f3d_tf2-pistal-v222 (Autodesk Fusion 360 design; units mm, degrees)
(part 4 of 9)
sketch "Sketch61" plane through (12.7981, 0, 0) normal (1, 0, 0) x axis (0, 1, 0)
  line L1 (189.658, -22.0959) -> (189.51, -21.9548)
  curve K1 (190.0964, -23.2203) -> (189.658, -22.0959)
  curve K2 (188.683, -22.9135) -> (189.7139, -23.5411)
  line L2 (188.5699, -22.7433) -> (188.683, -22.9135)
  line L3 (187.8606, -23.3644) -> (187.778, -23.1775)
  curve K3 (187.8354, -24.571) -> (187.8606, -23.3644)
  curve K4 (186.647, -23.7467) -> (187.3593, -24.721)
  line L4 (186.6076, -23.5461) -> (186.647, -23.7467)
  line L5 (185.7147, -23.8486) -> (185.7098, -23.6442)
  curve K5 (185.2296, -24.9537) -> (185.7147, -23.8486)
  curve K6 (184.4472, -23.7374) -> (184.7324, -24.91)
  line L6 (184.4875, -23.537) -> (184.4472, -23.7374)
  line L7 (183.5468, -23.4747) -> (183.6205, -23.284)
  curve K7 (182.6757, -24.31) -> (183.5468, -23.4747)
  curve K8 (182.4183, -22.8869) -> (182.233, -24.0794)
  line L8 (182.5323, -22.7172) -> (182.4183, -22.8869)
  line L9 (181.687, -22.2996) -> (181.8281, -22.1517)
  curve K9 (180.5626, -22.738) -> (181.687, -22.2996)
  curve K10 (180.8694, -21.3247) -> (180.2419, -22.3555)
  line L10 (181.0396, -21.2115) -> (180.8694, -21.3247)
  line L11 (180.4185, -20.5023) -> (180.6054, -20.4196)
  curve K11 (179.2119, -20.477) -> (180.4185, -20.5023)
  curve K12 (180.0362, -19.2887) -> (179.0619, -20.0009)
  line L12 (180.2368, -19.2493) -> (180.0362, -19.2887)
  line L13 (179.9343, -18.3563) -> (180.1387, -18.3515)
  curve K13 (178.8293, -17.8713) -> (179.9343, -18.3563)
  curve K14 (180.0455, -17.0888) -> (178.8729, -17.374)
  line L14 (180.246, -17.1292) -> (180.0455, -17.0888)
  line L15 (180.3082, -16.1884) -> (180.4989, -16.2622)
  curve K15 (179.4729, -15.3174) -> (180.3082, -16.1884)
  curve K16 (180.8961, -15.06) -> (179.7035, -14.8747)
  line L16 (181.0658, -15.1739) -> (180.8961, -15.06)
  line L17 (181.4833, -14.3287) -> (181.6312, -14.4698)
  curve K17 (181.0449, -13.2043) -> (181.4833, -14.3287)
  curve K18 (182.4582, -13.511) -> (181.4274, -12.8835)
  line L18 (182.5714, -13.6813) -> (182.4582, -13.511)
  line L19 (183.2806, -13.0601) -> (183.3633, -13.2471)
  curve K19 (183.3059, -11.8536) -> (183.2806, -13.0601)
  curve K20 (184.4942, -12.6778) -> (183.782, -11.7036)
  line L20 (184.5336, -12.8784) -> (184.4942, -12.6778)
  line L21 (185.4266, -12.576) -> (185.4314, -12.7803)
  curve K21 (185.9117, -11.4709) -> (185.4266, -12.576)
  curve K22 (186.6941, -12.6872) -> (186.4089, -11.5145)
  line L22 (186.6538, -12.8876) -> (186.6941, -12.6872)
  line L23 (187.5945, -12.9499) -> (187.5207, -13.1406)
  curve K23 (188.4655, -12.1146) -> (187.5945, -12.9499)
  curve K24 (188.723, -13.5377) -> (188.9082, -12.3452)
  line L24 (188.609, -13.7074) -> (188.723, -13.5377)
  line L25 (189.4543, -14.125) -> (189.3132, -14.2729)
  curve K25 (190.5787, -13.6866) -> (189.4543, -14.125)
  curve K26 (190.2719, -15.0999) -> (190.8994, -14.069)
  line L26 (190.1016, -15.2131) -> (190.2719, -15.0999)
  line L27 (190.7228, -15.9223) -> (190.5358, -16.005)
  curve K27 (191.9294, -15.9475) -> (190.7228, -15.9223)
  curve K28 (191.1051, -17.1359) -> (192.0793, -16.4236)
  line L28 (190.9045, -17.1753) -> (191.1051, -17.1359)
  line L29 (191.207, -18.0682) -> (191.0026, -18.0731)
  curve K29 (192.312, -18.5533) -> (191.207, -18.0682)
  curve K30 (191.0957, -19.3358) -> (192.2684, -19.0506)
  line L30 (190.8953, -19.2954) -> (191.0957, -19.3358)
  line L31 (190.833, -20.2361) -> (190.6424, -20.1624)
  curve K31 (191.6684, -21.1072) -> (190.833, -20.2361)
  curve K32 (190.2452, -21.3646) -> (191.4377, -21.5499)
  line L32 (190.0755, -21.2506) -> (190.2452, -21.3646)
  line L33 (187.271, -51.9985) -> (187.2458, -51.5038)
  curve K33 (189.5851, -57.0051) -> (187.271, -51.9985)
  curve K34 (192.6554, -51.291) -> (191.7132, -56.7255)
  line L34 (192.552, -50.8067) -> (192.6554, -51.291)
  line L35 (195.9575, -50.4071) -> (195.8052, -49.9359)
  curve K35 (199.4886, -54.6443) -> (195.9575, -50.4071)
  curve K36 (200.9754, -48.3302) -> (201.4718, -53.8234)
  line L36 (200.7501, -47.8891) -> (200.9754, -48.3302)
  line L37 (203.9362, -46.6218) -> (203.6671, -46.206)
  curve K37 (208.4437, -49.8007) -> (203.9362, -46.6218)
  curve K38 (208.2456, -43.3169) -> (210.1468, -48.4945)
  line L38 (207.9138, -42.9492) -> (208.2456, -43.3169)
  line L39 (210.6634, -40.9004) -> (210.2958, -40.5684)
  curve K39 (215.8399, -42.8043) -> (210.6634, -40.9004)
  curve K40 (213.9705, -36.5928) -> (217.147, -41.1018)
  line L40 (213.5549, -36.3234) -> (213.9705, -36.5928)
  line L41 (215.6805, -33.6328) -> (215.2395, -33.4073)
  curve K41 (221.1734, -34.1321) -> (215.6805, -33.6328)
  curve K42 (217.7601, -28.616) -> (221.9953, -32.1493)
  line L42 (217.2889, -28.4635) -> (217.7601, -28.616)
  line L43 (218.6457, -25.3144) -> (218.1614, -25.2107)
  curve K43 (224.0807, -24.375) -> (218.6457, -25.3144)
  curve K44 (219.3559, -19.9303) -> (224.3614, -22.247)
  line L44 (218.8613, -19.9049) -> (219.3559, -19.9303)
  line L45 (219.3568, -16.512) -> (218.8622, -16.5371)
  curve K45 (224.3635, -14.1979) -> (219.3568, -16.512)
  curve K46 (218.6494, -11.1275) -> (224.0839, -12.0698)
  line L46 (218.165, -11.231) -> (218.6494, -11.1275)
  line L47 (217.7655, -7.8254) -> (217.2942, -7.9777)
  curve K47 (222.0026, -4.2943) -> (217.7655, -7.8254)
  curve K48 (215.6886, -2.8075) -> (221.1818, -2.3111)
  line L48 (215.2475, -3.0328) -> (215.6886, -2.8075)
  line L49 (213.9802, 0.1533) -> (213.5644, -0.1158)
  curve K49 (217.159, 4.6607) -> (213.9802, 0.1533)
  curve K50 (210.6753, 4.4627) -> (215.8528, 6.3639)
  line L50 (210.3075, 4.1309) -> (210.6753, 4.4627)
  line L51 (208.2588, 6.8805) -> (207.9268, 6.5129)
  curve K51 (210.1627, 12.057) -> (208.2588, 6.8805)
  curve K52 (203.9511, 10.1876) -> (208.4602, 13.3641)
  line L52 (203.6818, 9.772) -> (203.9511, 10.1876)
  line L53 (200.9912, 11.8976) -> (200.7657, 11.4566)
  curve K53 (201.4905, 17.3905) -> (200.9912, 11.8976)
  curve K54 (195.9744, 13.9771) -> (199.5077, 18.2124)
  line L54 (195.8218, 13.5059) -> (195.9744, 13.9771)
  line L55 (192.6728, 14.8627) -> (192.569, 14.3784)
  curve K55 (191.7333, 20.2977) -> (192.6728, 14.8627)
  curve K56 (187.2887, 15.573) -> (189.6054, 20.5784)
  line L56 (187.2632, 15.0784) -> (187.2887, 15.573)
  line L57 (183.8703, 15.5739) -> (183.8955, 15.0793)
  curve K57 (181.5562, 20.5806) -> (183.8703, 15.5739)
  curve K58 (178.4858, 14.8664) -> (179.4281, 20.301)
  line L58 (178.5893, 14.3821) -> (178.4858, 14.8664)
  line L59 (175.1837, 13.9826) -> (175.3361, 13.5113)
  curve K59 (171.6527, 18.2197) -> (175.1837, 13.9826)
  curve K60 (170.1658, 11.9056) -> (169.6695, 17.3988)
  line L60 (170.3911, 11.4646) -> (170.1658, 11.9056)
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copy_paste_bodies "CopyPasteBodies4"
delete_face "DeleteFace52"
split "Split23"
delete_face "DeleteFace53"
delete_face "DeleteFace54"
move "Move3"
move "Move45"
sketch "Sketch62" plane through (9.6845, 0, 0) normal (1, 0, 0) x axis (0, 1, 0)
  line L1 (154.482, 22.4851) -> (154.482, 14)
  line L2 (20.5955, 22.4851) -> (154.482, 22.4851)
  line L3 (20.5955, 2.4851) -> (20.5955, 22.4851)
  line L4 (154.482, 2.4851) -> (20.5955, 2.4851)
  line L5 (154.482, 10) -> (154.482, 2.4851)
  line L6 (87.482, 10) -> (154.482, 10)
  line L7 (153.482, 13) -> (87.482, 13)
  arc A1 centre (87.482, 11.5) radius 1.5 clockwise from (87.482, 10) to (87.482, 13)
  arc A2 centre (153.482, 14) radius 1 clockwise from (154.482, 14) to (153.482, 13)
move "Move46" RotateAngle -30
move "Move4"
move "Move47" TranslateX 0 TranslateY -2 TranslateZ 0
combine "Combine51"
combine "Combine52"
delete_face "DeleteFace55"
delete_face "DeleteFace56"
fillet "Fillet76" radius 2
move_face "MoveFace72"
move "Move48"
move_face "MoveFace73"
move_face "MoveFace74"
move_face "MoveFace75"
move_face "MoveFace76"
delete_face "DeleteFace57"
move "Move5"
sketch "Sketch63" plane through (0, 18.7817, 0) normal (0, -1, 0) x axis (1, 0, 0)
  line L1 (8.6845, 2.4851) -> (-8.4524, 2.4851)
  line L2 (8.6845, 22.4851) -> (8.6845, 2.4851)
  line L3 (-8.4524, 22.4851) -> (8.6845, 22.4851)
  line L4 (-8.4524, 2.4851) -> (-8.4524, 22.4851)
  circle C1 centre (0, 12.7351) radius 5.9036
extrude "Extrude56" cut sketch "Sketch63" profile of C1 against normal blind 133.887
offset_faces "OffsetFaces8" distance -1
fillet "Fillet77" radius 1.5
fillet "Fillet78" radius 0.5
fillet "Fillet79" radius 0.5
delete_face "DeleteFace58"
move_face "MoveFace77"
delete_face "DeleteFace59"
move_face "MoveFace78"
move_face "MoveFace79"
move_face "MoveFace80"
remove_body "RemoveBody17"
copy_paste_bodies "CopyPasteBodies5"
copy_paste_bodies "CopyPasteBodies6"
move "Move49"
move "Move50"
delete_face "DeleteFace60"
delete_face "DeleteFace61"
delete_face "DeleteFace62"
move_face "MoveFace81"
delete_face "DeleteFace63"
move_face "MoveFace2"
combine "Combine53" bodies "Grip base"
remove_body "RemoveBody18"
combine "Combine54"
remove_body "RemoveBody19"
remove_body "RemoveBody20"
remove_body "RemoveBody21"
split "Split24"
remove_body "RemoveBody1"
remove_body "RemoveBody22"
remove_body "RemoveBody23"
move "Move51"
move_face "MoveFace3"
remove_body "RemoveBody24"
remove_body "RemoveBody25"
copy_paste_bodies "CopyPasteBodies8"
move "Move52"
combine "Combine55"
delete_face "DeleteFace64"
extrude "Extrude57" add of existing geometry blind 10
move_face "MoveFace83"
sketch "Sketch64" plane through (12.7981, 0, 0) normal (1, 0, 0) x axis (0, 1, 0)
  line L1 (89.7253, 20.0686) -> (89.7649, 20.5623)
  curve K1 (91.3661, 14.8028) -> (89.7253, 20.0686)
  curve K2 (95.156, 20.0672) -> (93.5125, 14.8022)
  line L2 (95.1167, 20.5609) -> (95.156, 20.0672)
  line L3 (98.2082, 21.6343) -> (96.0036, 21.6343)
  line L4 (99.0393, 20.0686) -> (99.0789, 20.5623)
  curve K3 (100.6801, 14.8028) -> (99.0393, 20.0686)
  curve K4 (104.47, 20.0672) -> (102.8265, 14.8022)
  line L5 (104.4307, 20.5609) -> (104.47, 20.0672)
  line L6 (107.5222, 21.6343) -> (105.3176, 21.6343)
  line L7 (108.3533, 20.0686) -> (108.3929, 20.5623)
  curve K5 (109.9941, 14.8028) -> (108.3533, 20.0686)
  curve K6 (113.784, 20.0672) -> (112.1405, 14.8022)
  line L8 (113.7447, 20.5609) -> (113.784, 20.0672)
  line L9 (116.8362, 21.6343) -> (114.6316, 21.6343)
  line L10 (117.6673, 20.0686) -> (117.7069, 20.5623)
  curve K7 (119.3081, 14.8028) -> (117.6673, 20.0686)
  curve K8 (123.098, 20.0672) -> (121.4545, 14.8022)
  line L11 (123.0587, 20.5609) -> (123.098, 20.0672)
  line L12 (126.1502, 21.6343) -> (123.9456, 21.6343)
  line L13 (126.9813, 20.0686) -> (127.0209, 20.5623)
  curve K9 (128.6221, 14.8028) -> (126.9813, 20.0686)
  curve K10 (132.412, 20.0672) -> (130.7685, 14.8022)
  line L14 (132.3727, 20.5609) -> (132.412, 20.0672)
  line L15 (135.4642, 21.6343) -> (133.2596, 21.6343)
  line L16 (136.2953, 20.0686) -> (136.3349, 20.5623)
  curve K11 (137.9361, 14.8028) -> (136.2953, 20.0686)
  curve K12 (141.726, 20.0672) -> (140.0825, 14.8022)
  line L17 (141.6867, 20.5609) -> (141.726, 20.0672)
  line L18 (144.7782, 21.6343) -> (142.5736, 21.6343)
  line L19 (145.6093, 20.0686) -> (145.6489, 20.5623)
  curve K13 (147.2501, 14.8028) -> (145.6093, 20.0686)
  curve K14 (151.04, 20.0672) -> (149.3965, 14.8022)
  line L20 (151.0007, 20.5609) -> (151.04, 20.0672)
  line L21 (154.0922, 21.6343) -> (151.8876, 21.6343)
  line L22 (154.9233, 20.0686) -> (154.9629, 20.5623)
  curve K15 (156.5641, 14.8028) -> (154.9233, 20.0686)
  curve K16 (160.354, 20.0672) -> (158.7105, 14.8022)
  line L23 (160.3147, 20.5609) -> (160.354, 20.0672)
  line L24 (163.4062, 21.6343) -> (161.2016, 21.6343)
  line L25 (164.2373, 20.0686) -> (164.2769, 20.5623)
  curve K17 (165.8781, 14.8028) -> (164.2373, 20.0686)
  curve K18 (169.668, 20.0672) -> (168.0245, 14.8022)
  line L26 (169.6287, 20.5609) -> (169.668, 20.0672)
  line L27 (172.7202, 21.6343) -> (170.5156, 21.6343)
  line L28 (173.5513, 20.0686) -> (173.5909, 20.5623)
  curve K19 (175.1921, 14.8028) -> (173.5513, 20.0686)
  curve K20 (178.982, 20.0672) -> (177.3385, 14.8022)
  line L29 (178.9427, 20.5609) -> (178.982, 20.0672)
  line L30 (182.0342, 21.6343) -> (179.8296, 21.6343)
  line L31 (182.8653, 20.0686) -> (182.9049, 20.5623)
  curve K21 (184.5061, 14.8028) -> (182.8653, 20.0686)
  curve K22 (188.296, 20.0672) -> (186.6525, 14.8022)
  line L32 (188.2567, 20.5609) -> (188.296, 20.0672)
  line L33 (189.1436, 25) -> (189.1436, 21.6343)
  line L34 (79.058, 25) -> (189.1436, 25)
  line L35 (79.058, 21.5994) -> (79.058, 25)
  line L36 (89.058, 21.5994) -> (79.058, 21.5994)
  line L37 (79.058, 3.4244) -> (79.058, 21.5994)
  line L38 (84.058, 3.4244) -> (79.058, 3.4244)
  line L39 (84.058, 21.5994) -> (84.058, 3.4244)
  arc A1 centre (88.7681, 20.6423) radius 1 clockwise from (89.058, 21.5994) to (89.7649, 20.5623)
  arc A2 centre (92.4495, 53.7877) radius 39 clockwise from (93.5125, 14.8022) to (91.3661, 14.8028)
  arc A3 centre (96.1135, 20.6404) radius 1 clockwise from (95.1167, 20.5609) to (96.0036, 21.6343)
  arc A4 centre (98.0821, 20.6423) radius 1 clockwise from (98.2082, 21.6343) to (99.0789, 20.5623)
  arc A5 centre (101.7635, 53.7877) radius 39 clockwise from (102.8265, 14.8022) to (100.6801, 14.8028)
  arc A6 centre (105.4275, 20.6404) radius 1 clockwise from (104.4307, 20.5609) to (105.3176, 21.6343)
  arc A7 centre (107.3961, 20.6423) radius 1 clockwise from (107.5222, 21.6343) to (108.3929, 20.5623)
  arc A8 centre (111.0775, 53.7877) radius 39 clockwise from (112.1405, 14.8022) to (109.9941, 14.8028)
  arc A9 centre (114.7415, 20.6404) radius 1 clockwise from (113.7447, 20.5609) to (114.6316, 21.6343)
  arc A10 centre (116.7101, 20.6423) radius 1 clockwise from (116.8362, 21.6343) to (117.7069, 20.5623)
  arc A11 centre (120.3915, 53.7877) radius 39 clockwise from (121.4545, 14.8022) to (119.3081, 14.8028)
  arc A12 centre (124.0555, 20.6404) radius 1 clockwise from (123.0587, 20.5609) to (123.9456, 21.6343)
  arc A13 centre (126.0241, 20.6423) radius 1 clockwise from (126.1502, 21.6343) to (127.0209, 20.5623)
  arc A14 centre (129.7055, 53.7877) radius 39 clockwise from (130.7685, 14.8022) to (128.6221, 14.8028)
  arc A15 centre (133.3695, 20.6404) radius 1 clockwise from (132.3727, 20.5609) to (133.2596, 21.6343)
  arc A16 centre (135.3381, 20.6423) radius 1 clockwise from (135.4642, 21.6343) to (136.3349, 20.5623)
  arc A17 centre (139.0195, 53.7877) radius 39 clockwise from (140.0825, 14.8022) to (137.9361, 14.8028)
  arc A18 centre (142.6835, 20.6404) radius 1 clockwise from (141.6867, 20.5609) to (142.5736, 21.6343)
  arc A19 centre (144.6521, 20.6423) radius 1 clockwise from (144.7782, 21.6343) to (145.6489, 20.5623)
  arc A20 centre (148.3335, 53.7877) radius 39 clockwise from (149.3965, 14.8022) to (147.2501, 14.8028)
  arc A21 centre (151.9975, 20.6404) radius 1 clockwise from (151.0007, 20.5609) to (151.8876, 21.6343)
  arc A22 centre (153.9661, 20.6423) radius 1 clockwise from (154.0922, 21.6343) to (154.9629, 20.5623)
  arc A23 centre (157.6475, 53.7877) radius 39 clockwise from (158.7105, 14.8022) to (156.5641, 14.8028)
  arc A24 centre (161.3115, 20.6404) radius 1 clockwise from (160.3147, 20.5609) to (161.2016, 21.6343)
  arc A25 centre (163.2801, 20.6423) radius 1 clockwise from (163.4062, 21.6343) to (164.2769, 20.5623)
  arc A26 centre (166.9615, 53.7877) radius 39 clockwise from (168.0245, 14.8022) to (165.8781, 14.8028)
  arc A27 centre (170.6255, 20.6404) radius 1 clockwise from (169.6287, 20.5609) to (170.5156, 21.6343)
  arc A28 centre (172.5941, 20.6423) radius 1 clockwise from (172.7202, 21.6343) to (173.5909, 20.5623)
  arc A29 centre (176.2755, 53.7877) radius 39 clockwise from (177.3385, 14.8022) to (175.1921, 14.8028)
  arc A30 centre (179.9395, 20.6404) radius 1 clockwise from (178.9427, 20.5609) to (179.8296, 21.6343)
  arc A31 centre (181.9081, 20.6423) radius 1 clockwise from (182.0342, 21.6343) to (182.9049, 20.5623)
  arc A32 centre (185.5895, 53.7877) radius 39 clockwise from (186.6525, 14.8022) to (184.5061, 14.8028)
  arc A33 centre (189.2535, 20.6404) radius 1 clockwise from (188.2567, 20.5609) to (189.1436, 21.6343)
  point P125 (79.058, 21.5994)
  point P126 (79.058, 21.5994)
  point P129 (84.058, 21.5994)
  coincident P125 P126
  perpendicular L36 L37
  perpendicular L37 L38
  midpoint L36 P129
  perpendicular L36 L39
extrude "Extrude58" add sketch "Sketch64" profile of L36 L37 L38 L39 against normal blind 3
extrude "Extrude59" cut of existing geometry blind -3
move_face "MoveFace84"
move_face "MoveFace85"
move_face "MoveFace86"
move_face "MoveFace87"
fillet "Fillet80" radius 39.5
move_face "MoveFace88"
sketch "Sketch65" plane through (12.7981, 0, 0) normal (1, 0, 0) x axis (0, 1, 0)
  line L1 (89.7253, 20.0686) -> (89.7649, 20.5623)
  curve K1 (91.3661, 14.8028) -> (89.7253, 20.0686)
  curve K2 (95.156, 20.0672) -> (93.5125, 14.8022)
  line L2 (95.1167, 20.5609) -> (95.156, 20.0672)
  line L3 (98.2082, 21.6343) -> (96.0036, 21.6343)
  line L4 (99.0393, 20.0686) -> (99.0789, 20.5623)
  curve K3 (100.6801, 14.8028) -> (99.0393, 20.0686)
  curve K4 (104.47, 20.0672) -> (102.8265, 14.8022)
  line L5 (104.4307, 20.5609) -> (104.47, 20.0672)
  line L6 (107.5222, 21.6343) -> (105.3176, 21.6343)
  line L7 (108.3533, 20.0686) -> (108.3929, 20.5623)
  curve K5 (109.9941, 14.8028) -> (108.3533, 20.0686)
  curve K6 (113.784, 20.0672) -> (112.1405, 14.8022)
  line L8 (113.7447, 20.5609) -> (113.784, 20.0672)
  line L9 (116.8362, 21.6343) -> (114.6316, 21.6343)
  line L10 (117.6673, 20.0686) -> (117.7069, 20.5623)
  curve K7 (119.3081, 14.8028) -> (117.6673, 20.0686)
  curve K8 (123.098, 20.0672) -> (121.4545, 14.8022)
  line L11 (123.0587, 20.5609) -> (123.098, 20.0672)
  line L12 (126.1502, 21.6343) -> (123.9456, 21.6343)
  line L13 (126.9813, 20.0686) -> (127.0209, 20.5623)
  curve K9 (128.6221, 14.8028) -> (126.9813, 20.0686)
  curve K10 (132.412, 20.0672) -> (130.7685, 14.8022)
  line L14 (132.3727, 20.5609) -> (132.412, 20.0672)
  line L15 (135.4642, 21.6343) -> (133.2596, 21.6343)
  line L16 (136.2953, 20.0686) -> (136.3349, 20.5623)
  curve K11 (137.9361, 14.8028) -> (136.2953, 20.0686)
  curve K12 (141.726, 20.0672) -> (140.0825, 14.8022)
  line L17 (141.6867, 20.5609) -> (141.726, 20.0672)
  line L18 (144.7782, 21.6343) -> (142.5736, 21.6343)
  line L19 (145.6093, 20.0686) -> (145.6489, 20.5623)
  curve K13 (147.2501, 14.8028) -> (145.6093, 20.0686)
  curve K14 (151.04, 20.0672) -> (149.3965, 14.8022)
  line L20 (151.0007, 20.5609) -> (151.04, 20.0672)
  line L21 (154.0922, 21.6343) -> (151.8876, 21.6343)
  line L22 (154.9233, 20.0686) -> (154.9629, 20.5623)
  curve K15 (156.5641, 14.8028) -> (154.9233, 20.0686)
  curve K16 (160.354, 20.0672) -> (158.7105, 14.8022)
  line L23 (160.3147, 20.5609) -> (160.354, 20.0672)
  line L24 (163.4062, 21.6343) -> (161.2016, 21.6343)
  line L25 (164.2373, 20.0686) -> (164.2769, 20.5623)
  curve K17 (165.8781, 14.8028) -> (164.2373, 20.0686)
  curve K18 (169.668, 20.0672) -> (168.0245, 14.8022)
  line L26 (169.6287, 20.5609) -> (169.668, 20.0672)
  line L27 (172.7202, 21.6343) -> (170.5156, 21.6343)
  line L28 (173.5513, 20.0686) -> (173.5909, 20.5623)
  curve K19 (175.1921, 14.8028) -> (173.5513, 20.0686)
  curve K20 (178.982, 20.0672) -> (177.3385, 14.8022)
  line L29 (178.9427, 20.5609) -> (178.982, 20.0672)
  line L30 (182.0342, 21.6343) -> (179.8296, 21.6343)
  line L31 (182.8653, 20.0686) -> (182.9049, 20.5623)
  curve K21 (184.5061, 14.8028) -> (182.8653, 20.0686)
  curve K22 (188.296, 20.0672) -> (186.6525, 14.8022)
  line L32 (188.2567, 20.5609) -> (188.296, 20.0672)
  line L33 (189.1436, 25) -> (189.1436, 21.6343)
  line L34 (79.058, 25) -> (189.1436, 25)
  line L35 (79.058, 2.0244) -> (79.058, 25)
  line L36 (82.12, 2.0244) -> (79.058, 2.0244)
  line L37 (96.9801, 21.6343) -> (89.058, 21.5994)
  line L38 (89.5944, 13.3135) -> (89.058, 21.5994)
  line L39 (96.7779, 13.7786) -> (89.5944, 13.3135)
  line L40 (96.9801, 21.6343) -> (96.7779, 13.7786)
  arc A1 centre (88.7681, 20.6423) radius 1 clockwise from (89.058, 21.5994) to (89.7649, 20.5623)
  arc A2 centre (92.4495, 53.7877) radius 39 clockwise from (93.5125, 14.8022) to (91.3661, 14.8028)
  arc A3 centre (96.1135, 20.6404) radius 1 clockwise from (95.1167, 20.5609) to (96.0036, 21.6343)
  arc A4 centre (98.0821, 20.6423) radius 1 clockwise from (98.2082, 21.6343) to (99.0789, 20.5623)
  arc A5 centre (101.7635, 53.7877) radius 39 clockwise from (102.8265, 14.8022) to (100.6801, 14.8028)
  arc A6 centre (105.4275, 20.6404) radius 1 clockwise from (104.4307, 20.5609) to (105.3176, 21.6343)
  arc A7 centre (107.3961, 20.6423) radius 1 clockwise from (107.5222, 21.6343) to (108.3929, 20.5623)
  arc A8 centre (111.0775, 53.7877) radius 39 clockwise from (112.1405, 14.8022) to (109.9941, 14.8028)
  arc A9 centre (114.7415, 20.6404) radius 1 clockwise from (113.7447, 20.5609) to (114.6316, 21.6343)
  arc A10 centre (116.7101, 20.6423) radius 1 clockwise from (116.8362, 21.6343) to (117.7069, 20.5623)
  arc A11 centre (120.3915, 53.7877) radius 39 clockwise from (121.4545, 14.8022) to (119.3081, 14.8028)
  arc A12 centre (124.0555, 20.6404) radius 1 clockwise from (123.0587, 20.5609) to (123.9456, 21.6343)
  arc A13 centre (126.0241, 20.6423) radius 1 clockwise from (126.1502, 21.6343) to (127.0209, 20.5623)
  arc A14 centre (129.7055, 53.7877) radius 39 clockwise from (130.7685, 14.8022) to (128.6221, 14.8028)
  arc A15 centre (133.3695, 20.6404) radius 1 clockwise from (132.3727, 20.5609) to (133.2596, 21.6343)
  arc A16 centre (135.3381, 20.6423) radius 1 clockwise from (135.4642, 21.6343) to (136.3349, 20.5623)
  arc A17 centre (139.0195, 53.7877) radius 39 clockwise from (140.0825, 14.8022) to (137.9361, 14.8028)
  arc A18 centre (142.6835, 20.6404) radius 1 clockwise from (141.6867, 20.5609) to (142.5736, 21.6343)
  arc A19 centre (144.6521, 20.6423) radius 1 clockwise from (144.7782, 21.6343) to (145.6489, 20.5623)
  arc A20 centre (148.3335, 53.7877) radius 39 clockwise from (149.3965, 14.8022) to (147.2501, 14.8028)
  arc A21 centre (151.9975, 20.6404) radius 1 clockwise from (151.0007, 20.5609) to (151.8876, 21.6343)
  arc A22 centre (153.9661, 20.6423) radius 1 clockwise from (154.0922, 21.6343) to (154.9629, 20.5623)
  arc A23 centre (157.6475, 53.7877) radius 39 clockwise from (158.7105, 14.8022) to (156.5641, 14.8028)
  arc A24 centre (161.3115, 20.6404) radius 1 clockwise from (160.3147, 20.5609) to (161.2016, 21.6343)
  arc A25 centre (163.2801, 20.6423) radius 1 clockwise from (163.4062, 21.6343) to (164.2769, 20.5623)
  arc A26 centre (166.9615, 53.7877) radius 39 clockwise from (168.0245, 14.8022) to (165.8781, 14.8028)
  arc A27 centre (170.6255, 20.6404) radius 1 clockwise from (169.6287, 20.5609) to (170.5156, 21.6343)
  arc A28 centre (172.5941, 20.6423) radius 1 clockwise from (172.7202, 21.6343) to (173.5909, 20.5623)
  arc A29 centre (176.2755, 53.7877) radius 39 clockwise from (177.3385, 14.8022) to (175.1921, 14.8028)
  arc A30 centre (179.9395, 20.6404) radius 1 clockwise from (178.9427, 20.5609) to (179.8296, 21.6343)
  arc A31 centre (181.9081, 20.6423) radius 1 clockwise from (182.0342, 21.6343) to (182.9049, 20.5623)
  arc A32 centre (185.5895, 53.7877) radius 39 clockwise from (186.6525, 14.8022) to (184.5061, 14.8028)
  arc A33 centre (189.2535, 20.6404) radius 1 clockwise from (188.2567, 20.5609) to (189.1436, 21.6343)
  arc A34 centre (121.5101, -0.9197) radius 39.5 clockwise from (82.12, 2.0244) to (89.058, 21.5994)
  point P3 (89.058, 21.5994)
  point P128 (89.058, 21.5994)
  coincident P3 P128
  perpendicular L38 L39
extrude "Extrude60" cut sketch "Sketch65" profile of A1 L1 K1 A2 K2 L2 A3 L37 L38 L39 L40 against normal blind 3
fillet "Fillet81" radius 2
fillet "Fillet82" radius 1
move "Move53" RotateAngle 30
sketch "Sketch66" plane through (8.6845, 0, 0) normal (1, 0, 0) x axis (0, 1, 0)
  line L1 (19.0955, 22) -> (151.1682, 22)
  line L2 (19.0955, 1) -> (19.0955, 22)
  line L3 (151.1682, 1) -> (19.0955, 1)
  line L4 (151.1682, 8.5) -> (151.1682, 1)
  line L5 (85.6682, 8.5) -> (151.1682, 8.5)
  line L6 (151.1682, 14.5) -> (85.6682, 14.5)
  line L7 (151.1682, 22) -> (151.1682, 14.5)
  line L8 (154, 4.75) -> (152.7544, 4.75)
  line L9 (154, 1) -> (154, 4.75)
  line L10 (152.7544, 1) -> (154, 1)
  line L11 (152.7544, 4.75) -> (152.7544, 1)
  arc A1 centre (85.6682, 11.5) radius 3 clockwise from (85.6682, 8.5) to (85.6682, 14.5)
  horizontal L8
  vertical L9
  horizontal L10
  vertical L11
extrude "Extrude61" new body sketch "Sketch66" profile of L8 L9 L10 L11 blind -3.684 from offset -5
mirror "Mirror19" mirrorStitchTolerance 0.1
combine "Combine56"
move "Move54"
move "Move55"
move "Move56"
combine "Combine57"
combine "Combine58"
move "Move57"
combine "Combine59"
mirror "Mirror20" mirrorStitchTolerance 0.1
sketch "Sketch67" plane through (8.6845, 0, 0) normal (1, 0, 0) x axis (0, 1, 0)
  line L1 (19.0955, 22) -> (151.1682, 22)
  line L2 (19.0955, 1) -> (19.0955, 22)
  line L3 (151.1682, 1) -> (19.0955, 1)
  line L4 (151.1682, 8.5) -> (151.1682, 1)
  line L5 (85.6682, 8.5) -> (151.1682, 8.5)
  line L6 (151.1682, 14.5) -> (85.6682, 14.5)
  line L7 (151.1682, 22) -> (151.1682, 14.5)
  arc A1 centre (85.6682, 11.5) radius 3 clockwise from (85.6682, 8.5) to (85.6682, 14.5)
  circle C1 centre (153.2, 5.6) radius 1.0296
move_face "MoveFace89"
sketch "Sketch68" plane through (0, 0, 25) normal (0, 0, 1) x axis (-1, 0, 0)
  line L1 (9.7981, -189.1436) -> (9.7981, -70.058)
  line L2 (12.7981, -189.1436) -> (9.7981, -189.1436)
  line L3 (12.7981, -70.058) -> (12.7981, -189.1436)
  line L4 (9.7981, -70.058) -> (12.7981, -70.058)
  line L5 (9.7981, -189.1436) -> (12.7981, -189.1436)
  line L6 (12.7981, -189.1436) -> (12.7981, -70.058)
  line L7 (-9.7981, -70.058) -> (-12.7981, -70.058)
  line L8 (-12.7981, -189.1436) -> (-12.7981, -70.058)
  line L9 (12.7981, -70.058) -> (-12.7981, -70.058)
  line L10 (12.7981, -189.1436) -> (12.7981, -70.058)
  line L11 (-12.7981, -189.1436) -> (12.7981, -189.1436)
  line L12 (-12.7981, -70.058) -> (-12.7981, -189.1436)
  point P6 (12.7981, -189.1436)
  point P14 (12.7981, -189.1436)
  point P9 (-12.7981, -70.058)
  point P12 (-12.7981, -70.058)
  horizontal L9
  vertical L10
  horizontal L11
  vertical L12
  coincident P6 P14
  coincident P9 P12
extrude "Extrude62" add sketch "Sketch68" against normal blind 2.7
move_face "MoveFace90"
move_face "MoveFace91"
sketch "Sketch69" plane through (17.9981, 0, 0) normal (1, 0, 0) x axis (0, 1, 0)
  line L1 (171.9916, -32.8813) -> (200.2987, -133.9094)
  curve K1 (155.8322, -35.7087) -> (157.7262, -38.8106)
  curve K2 (157.7262, -38.8106) -> (163.8476, -56.0881)
  curve K3 (163.8476, -56.0881) -> (163.931, -57.8793)
  line L2 (163.0153, -60.3193) -> (163.931, -57.8793)
  line L3 (143.9303, -157.3483) -> (163.0153, -60.3193)
  line L4 (151, 10) -> (152.7854, -17.6166)
  line L5 (154.9731, 10.2569) -> (151, 10)
  line L6 (164.454, -13.2268) -> (154.9731, 10.2569)
  arc A1 centre (162.3398, -25.3102) radius 12.267 clockwise from (155.8322, -35.7087) to (171.9916, -32.8813)
  arc A2 centre (162.3398, -25.3102) radius 133.3153 clockwise from (186.1858, -156.4755) to (143.9303, -157.3483)
  arc A3 centre (182.9662, -138.7658) radius 18 clockwise from (200.2987, -133.9094) to (186.1858, -156.4755)
  point P13 (152.7854, -17.6166)
  point P16 (164.454, -13.2268)
  coincident A1 P13
  perpendicular L4 L5
  coincident A1 P16
extrude "Extrude63" new body sketch "Sketch69" profile of A1 L4 L5 L6 against normal blind 5
sketch "Sketch70" plane through (17.9981, 0, 0) normal (1, 0, 0) x axis (0, 1, 0)
  line L1 (151, 10) -> (154.9731, 10.2569)
  line L2 (152.7854, -17.6166) -> (151, 10)
  line L3 (154.9731, 10.2569) -> (164.454, -13.2268)
  arc A1 centre (162.3398, -25.3102) radius 12.267 clockwise from (152.7854, -17.6166) to (164.454, -13.2268)
  circle C1 centre (185.5706, -18.2123) radius 39.1607
extrude "Extrude64" new body sketch "Sketch70" profile of L1 L2 L3 C1 against normal blind 9.314
move_face "MoveFace92" TranslateX 0 TranslateY -1 TranslateZ 0
move "Move58" TranslateX 0.5 TranslateY 0 TranslateZ 0
move_face "MoveFace93" TranslateX -0.5 TranslateY 0 TranslateZ 0
combine "Combine60"
fillet "Fillet83" radius 0.5
fillet "Fillet84" radius 0.5
fillet "Fillet85" radius 2
mirror "Mirror21" mirrorStitchTolerance 0.1
delete_face "DeleteFace65"
delete_face "DeleteFace66"
sketch "Sketch71" plane through (17.9981, 0, 0) normal (1, 0, 0) x axis (0, 1, 0)
  line L1 (154.6681, -15.7382) -> (153.1249, 8.1332)
  line L2 (153.6597, 8.1678) -> (162.2233, -13.0438)
  line L3 (153.1249, 8.1332) -> (153.6597, 8.1678)
  line L4 (152, -15) -> (162.3398, -25.3102)
  line L5 (162.3398, -25.3102) -> (152, -15)
  line L6 (162.3398, -25.3102) -> (164, -11)
  line L7 (147.6215, 8.7306) -> (162.3398, -25.3102)
  line L8 (128.0109, -11.2772) -> (162.3398, -25.3102)
  line L9 (129.8181, -7.4849) -> (149.1405, -19.9146)
  line L10 (166.6138, 11.5291) -> (162.3398, -25.3102)
  line L11 (156.9141, 11.3772) -> (164, -11)
  arc A1 centre (162.3398, -25.3102) radius 12.267 clockwise from (154.6681, -15.7382) to (162.2233, -13.0438)
  circle C1 centre (162.3398, -25.3102) radius 37.0864
  point P5 (162.3398, -25.3102)
  point P8 (162.3398, -25.3102)
  point P11 (147.6215, 8.7306)
  point P12 (128.0109, -11.2772)
  point P13 (149.1405, -19.9146)
  point P14 (129.8181, -7.4849)
  point P7 (162.3398, -25.3102)
  point P15 (162.3398, -25.3102)
  point P16 (166.6138, 11.5291)
  point P17 (156.9141, 11.3772)
  concentric A1 C1
  coincident P5 P8
  coincident C1 P11
  coincident C1 P12
  coincident L8 P13
  coincident C1 P14
  coincident P7 P15
  coincident C1 P16
  parallel L6 L10
  coincident C1 P17
  dimension "d581" angle L4 L6 = 51.7
  dimension "d582" angle L6 L7 = 30
extrude "Extrude65" new body sketch "Sketch71" profile of L1 A1 L2 L3 C1 L6 L7 L8 L9 L10 L11 against normal blind 9.314
mirror "Mirror22" mirrorStitchTolerance 0.1
combine "Combine61"
combine "Combine62"
extrude "Extrude66" cut of existing geometry blind -4.998
combine "Combine63"
combine "Combine64"
extrude "Extrude67" cut of existing geometry blind -4.998
move_face "MoveFace94"
move_face "MoveFace95" RotateAngle -30
sketch "Sketch72" plane through (0, 0, 1) normal (0, 0, 1) x axis (-1, 0, 0)
  line L1 (8.6841, -125.9366) -> (8.6841, -144.3129)
  line L2 (17.9981, -125.9366) -> (8.6841, -125.9366)
  line L3 (17.9981, -144.3129) -> (17.9981, -125.9366)
  line L4 (19.9973, -144.3129) -> (17.9981, -144.3129)
  line L5 (19.9973, -21.0955) -> (19.9973, -144.3129)
  line L6 (17.9973, -19.0955) -> (19.9973, -21.0955)
  line L7 (-17.9977, -19.0955) -> (17.9973, -19.0955)
  line L8 (-19.9977, -21.0955) -> (-17.9977, -19.0955)
  line L9 (-19.9977, -144.3129) -> (-19.9977, -21.0955)
  line L10 (-17.9981, -144.3129) -> (-19.9977, -144.3129)
  line L11 (-17.9981, -125.9366) -> (-17.9981, -144.3129)
  line L12 (-8.6841, -125.9366) -> (-17.9981, -125.9366)
  line L13 (-8.6841, -144.3129) -> (-8.6841, -125.9366)
  line L14 (8.6841, -144.3129) -> (-8.6841, -144.3129)
  line L15 (17.9981, -144.3129) -> (17.9981, -125.9366)
  line L16 (-17.9981, -125.9366) -> (-17.9981, -144.3129)
  line L17 (-17.9981, -70.058) -> (-17.9981, -125.9366)
  line L18 (12.7981, -70.058) -> (-17.9981, -70.058)
  line L19 (17.9981, -70.058) -> (17.9981, -125.9366)
  line L20 (12.7981, -70.058) -> (17.9981, -70.058)
  line L21 (8.4524, -19.0955) -> (8.4524, -141.9991)
  line L22 (-8.6845, -151.1682) -> (-8.6845, -19.0955)
  point P13 (-17.9981, -125.9366)
  point P22 (-17.9981, -125.9366)
  point P18 (12.7981, -70.058)
  point P24 (12.7981, -70.058)
  point P4 (17.9981, -125.9366)
  point P25 (17.9981, -125.9366)
  coincident P13 P22
  perpendicular L12 L17
  coincident P18 P24
  perpendicular L17 L18
  coincident P4 P25
  perpendicular L18 L19
  perpendicular L5 L20
extrude "Extrude68" new body sketch "Sketch72" profile of L3 L4 L5 L6 L7 L8 L9 L10 L11 L15 L16 L17 L18 L19 L20 L21 L22 along normal blind 9
chamfer "Chamfer23" distance 2
sketch "Sketch73" plane through (0, 0, 1) normal (0, 0, 1) x axis (-1, 0, 0)
  line L1 (8.6841, -125.9366) -> (8.6841, -144.3129)
  line L2 (17.9981, -125.9366) -> (8.6841, -125.9366)
  line L3 (17.9981, -144.3129) -> (17.9981, -125.9366)
  line L4 (19.9973, -144.3129) -> (17.9981, -144.3129)
  line L5 (19.9973, -21.0955) -> (19.9973, -144.3129)
  line L6 (17.9973, -19.0955) -> (19.9973, -21.0955)
  line L7 (-17.9977, -19.0955) -> (17.9973, -19.0955)
  line L8 (-19.9977, -21.0955) -> (-17.9977, -19.0955)
  line L9 (-19.9977, -144.3129) -> (-19.9977, -21.0955)
  line L10 (-17.9981, -144.3129) -> (-19.9977, -144.3129)
  line L11 (-17.9981, -125.9366) -> (-17.9981, -144.3129)
  line L12 (-8.6841, -125.9366) -> (-17.9981, -125.9366)
  line L13 (-8.6841, -144.3129) -> (-8.6841, -125.9366)
  line L14 (8.6841, -144.3129) -> (-8.6841, -144.3129)
  line L15 (-17.9981, -70.058) -> (-17.9977, -70.058)
  line L16 (-8.6845, -70.058) -> (-17.9981, -70.058)
  line L17 (-17.9977, -70.058) -> (-8.6845, -70.058)
  line L18 (-12.7981, -80.1147) -> (-12.7981, -70.058)
  line L19 (-12.7981, -86.6444) -> (-12.7981, -80.1147)
  line L20 (-12.7981, -95.9689) -> (-12.7981, -86.6444)
  line L21 (-12.7981, -95.9689) -> (-12.7981, -96.0036)
  line L22 (-12.7981, -98.2082) -> (-12.7981, -96.0036)
  line L23 (-12.7981, -98.2082) -> (-12.7981, -99.0821)
  line L24 (-12.7981, -99.0393) -> (-12.7981, -99.0789)
  line L25 (-12.7981, -100.6801) -> (-12.7981, -99.0343)
  line L26 (-12.7981, -102.8265) -> (-12.7981, -100.6801)
  line L27 (-12.7981, -104.475) -> (-12.7981, -102.8265)
  line L28 (-12.7981, -104.4307) -> (-12.7981, -104.47)
  line L29 (-12.7981, -104.4275) -> (-12.7981, -105.3176)
  line L30 (-12.7981, -107.5222) -> (-12.7981, -105.3176)
  line L31 (-12.7981, -107.5222) -> (-12.7981, -108.3961)
  line L32 (-12.7981, -108.3533) -> (-12.7981, -108.3929)
  line L33 (-12.7981, -109.9941) -> (-12.7981, -108.3483)
  line L34 (-12.7981, -112.1405) -> (-12.7981, -109.9941)
  line L35 (-12.7981, -113.789) -> (-12.7981, -112.1405)
  line L36 (-12.7981, -113.7447) -> (-12.7981, -113.784)
  line L37 (-12.7981, -113.7415) -> (-12.7981, -114.6316)
  line L38 (-12.7981, -116.8362) -> (-12.7981, -114.6316)
  line L39 (-12.7981, -116.8362) -> (-12.7981, -117.7101)
  line L40 (-12.7981, -117.6673) -> (-12.7981, -117.7069)
  line L41 (-12.7981, -119.3081) -> (-12.7981, -117.6623)
  line L42 (-12.7981, -121.4545) -> (-12.7981, -119.3081)
  line L43 (-12.7981, -123.103) -> (-12.7981, -121.4545)
  line L44 (-12.7981, -123.0587) -> (-12.7981, -123.098)
  line L45 (-12.7981, -123.0555) -> (-12.7981, -123.9456)
  line L46 (-12.7981, -126.1502) -> (-12.7981, -123.9456)
  line L47 (-12.7981, -126.1502) -> (-12.7981, -127.0241)
  line L48 (-12.7981, -126.9813) -> (-12.7981, -127.0209)
  line L49 (-12.7981, -128.6221) -> (-12.7981, -126.9763)
  line L50 (-12.7981, -130.7685) -> (-12.7981, -128.6221)
  line L51 (-12.7981, -132.417) -> (-12.7981, -130.7685)
  line L52 (-12.7981, -132.3727) -> (-12.7981, -132.412)
  line L53 (-12.7981, -132.3695) -> (-12.7981, -133.2596)
  line L54 (-12.7981, -135.4642) -> (-12.7981, -133.2596)
  line L55 (-12.7981, -135.4642) -> (-12.7981, -136.3381)
  line L56 (-12.7981, -136.2953) -> (-12.7981, -136.3349)
  line L57 (-12.7981, -137.9361) -> (-12.7981, -136.2903)
  line L58 (-12.7981, -140.0825) -> (-12.7981, -137.9361)
  line L59 (-12.7981, -141.731) -> (-12.7981, -140.0825)
  line L60 (-12.7981, -141.6867) -> (-12.7981, -141.726)
  line L61 (-12.7981, -141.6835) -> (-12.7981, -142.5736)
  line L62 (-12.7981, -144.7782) -> (-12.7981, -142.5736)
  line L63 (-12.7981, -144.7782) -> (-12.7981, -145.6521)
  line L64 (-12.7981, -145.6093) -> (-12.7981, -145.6489)
  line L65 (-12.7981, -147.2501) -> (-12.7981, -145.6043)
  line L66 (-12.7981, -149.3965) -> (-12.7981, -147.2501)
  line L67 (-12.7981, -151.045) -> (-12.7981, -149.3965)
  line L68 (-12.7981, -151.0007) -> (-12.7981, -151.04)
  line L69 (-12.7981, -150.9975) -> (-12.7981, -151.8876)
  line L70 (-12.7981, -154.0922) -> (-12.7981, -151.8876)
  line L71 (-12.7981, -154.0922) -> (-12.7981, -154.9661)
  line L72 (-12.7981, -154.9233) -> (-12.7981, -154.9629)
  line L73 (-12.7981, -156.5641) -> (-12.7981, -154.9183)
  line L74 (-12.7981, -158.7105) -> (-12.7981, -156.5641)
  line L75 (-12.7981, -160.359) -> (-12.7981, -158.7105)
  line L76 (-12.7981, -160.3147) -> (-12.7981, -160.354)
  line L77 (-12.7981, -160.3115) -> (-12.7981, -161.2016)
  line L78 (-12.7981, -163.4062) -> (-12.7981, -161.2016)
  line L79 (-12.7981, -163.4062) -> (-12.7981, -164.2801)
  line L80 (-12.7981, -164.2373) -> (-12.7981, -164.2769)
  line L81 (-12.7981, -165.8781) -> (-12.7981, -164.2323)
  line L82 (-12.7981, -168.0245) -> (-12.7981, -165.8781)
  line L83 (-12.7981, -169.673) -> (-12.7981, -168.0245)
  line L84 (-12.7981, -169.6287) -> (-12.7981, -169.668)
  line L85 (-12.7981, -169.6255) -> (-12.7981, -170.5156)
  line L86 (-12.7981, -172.7202) -> (-12.7981, -170.5156)
  line L87 (-12.7981, -172.7202) -> (-12.7981, -173.5941)
  line L88 (-12.7981, -173.5513) -> (-12.7981, -173.5909)
  line L89 (-12.7981, -175.1921) -> (-12.7981, -173.5463)
  line L90 (-12.7981, -177.3385) -> (-12.7981, -175.1921)
  line L91 (-12.7981, -178.987) -> (-12.7981, -177.3385)
  line L92 (-12.7981, -178.9427) -> (-12.7981, -178.982)
  line L93 (-12.7981, -178.9395) -> (-12.7981, -179.8296)
  line L94 (-12.7981, -182.0342) -> (-12.7981, -179.8296)
  line L95 (-12.7981, -182.0342) -> (-12.7981, -182.9081)
  line L96 (-12.7981, -182.8653) -> (-12.7981, -182.9049)
  line L97 (-12.7981, -184.5061) -> (-12.7981, -182.8603)
  line L98 (-12.7981, -186.6525) -> (-12.7981, -184.5061)
  line L99 (-12.7981, -188.301) -> (-12.7981, -186.6525)
  line L100 (-12.7981, -188.2567) -> (-12.7981, -188.296)
  line L101 (-12.7981, -188.2535) -> (-12.7981, -189.1436)
  line L102 (-12.7981, -70.058) -> (-12.7981, -189.1436)
  line L103 (-17.9981, -144.3129) -> (-17.9981, -70.058)
  line L104 (-17.9981, -70.058) -> (-17.9981, -144.3129)
  line L105 (12.7981, -188.2535) -> (12.7981, -189.1436)
  line L106 (12.7981, -188.296) -> (12.7981, -188.2567)
  line L107 (12.7981, -188.301) -> (12.7981, -186.6525)
  line L108 (12.7981, -186.6525) -> (12.7981, -184.5061)
  line L109 (12.7981, -184.5061) -> (12.7981, -182.8603)
  line L110 (12.7981, -182.9049) -> (12.7981, -182.8653)
  line L111 (12.7981, -182.0342) -> (12.7981, -182.9081)
  line L112 (12.7981, -179.8296) -> (12.7981, -182.0342)
  line L113 (12.7981, -178.9395) -> (12.7981, -179.8296)
  line L114 (12.7981, -178.982) -> (12.7981, -178.9427)
  line L115 (12.7981, -178.987) -> (12.7981, -177.3385)
  line L116 (12.7981, -177.3385) -> (12.7981, -175.1921)
  line L117 (12.7981, -175.1921) -> (12.7981, -173.5463)
  line L118 (12.7981, -173.5909) -> (12.7981, -173.5513)
  line L119 (12.7981, -172.7202) -> (12.7981, -173.5941)
  line L120 (12.7981, -170.5156) -> (12.7981, -172.7202)
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  point P144 (-17.9981, -70.058)
  point P276 (-17.9981, -70.058)
  point P271 (17.9981, -70.058)
  point P280 (17.9981, -70.058)
  point P279 (-17.9981, -75.258)
  point P283 (17.9981, -75.258)
  coincident P144 P276
  coincident P271 P280
  dimension "d596" distance P276 P279 = 5.2
  dimension "d597" distance P280 P283 = 5.2
extrude "Extrude69" cut sketch "Sketch73" against normal blind 45
sketch "Sketch74" plane through (12.7981, 0, 0) normal (1, 0, 0) x axis (0, 1, 0)
  curve K1 (70.058, -24.8738) -> (75, -25)
  line L1 (75.258, -25) -> (75, -25)
  line L2 (75.258, 1) -> (75.258, -25)
  line L3 (70.058, 1) -> (75.258, 1)
  line L4 (70.058, -24.8738) -> (70.058, 1)
  line L5 (75.258, -24.8738) -> (70.058, -24.8738)
  line L6 (75.258, -19.6738) -> (75.258, -24.8738)
  line L7 (70.058, -19.6738) -> (75.258, -19.6738)
  line L8 (70.058, -24.8738) -> (70.058, -19.6738)
  line L9 (75.258, -24.8738) -> (70.058, -24.8738)
  line L10 (75.258, -28.4155) -> (75.258, -24.8738)
  line L11 (70.058, -28.4155) -> (75.258, -28.4155)
  line L12 (70.058, -24.8738) -> (70.058, -28.4155)
  point P9 (75.258, -19.6738)
  point P3 (70.058, -24.8738)
  point P7 (70.058, -24.8738)
  point P11 (70.058, -24.8738)
  point P10 (70.058, -19.6738)
  horizontal L5
  vertical L6
  horizontal L7
  vertical L8
  coincident L2 P9
  coincident P3 P7
  horizontal L9
  vertical L10
  horizontal L11
  vertical L12
  coincident P3 P11
  dimension "d600" distance P7 P10 = 5.2
extrude "Extrude70" cut sketch "Sketch74" profile of K1 L1 L2 L4 L5 L6 L7 L8 L9 L10 L11 L12 against normal blind 25.596
delete_face "DeleteFace67"
fillet "Fillet86" radius 5.2
fillet "Fillet87" radius 2.5
fillet "Fillet88" radius 0.3
move_face "MoveFace96"
move_face "MoveFace5"
chamfer "Chamfer24" distance 0.6656
extrude "Extrude71" new body of existing geometry blind 14
combine "Combine65"
delete_face "DeleteFace68"
delete_face "DeleteFace69"
move_face "MoveFace97" RotateAngle 45
move_face "MoveFace98" RotateAngle 45
delete_face "DeleteFace70"
copy_paste_bodies "CopyPasteBodies9"
copy_paste_bodies "CopyPasteBodies10"
copy_paste_bodies "CopyPasteBodies11"
combine "Combine66"
combine "Combine67"
move_face "MoveFace99"
delete_face "DeleteFace71"
move_face "MoveFace100"
move_face "MoveFace101"
move_face "MoveFace102"
delete_face "DeleteFace72"
move_face "MoveFace103"
combine "Combine68"
fillet "Fillet89" radius 0.25
chamfer "Chamfer25" distance 3
chamfer "Chamfer26" distance 3.4
combine "Combine69"
remove_body "RemoveBody26"
remove_body "RemoveBody27"
remove_body "RemoveBody28"
remove_body "RemoveBody29"
remove_body "RemoveBody30"
remove_body "RemoveBody31"
remove_body "RemoveBody32"
remove_body "RemoveBody33"
remove_body "RemoveBody34"
delete_face "DeleteFace73"
fillet "Fillet90" radius 2.25
delete_face "DeleteFace74"
fillet "Fillet91" radius 2.25
fillet "Fillet92" radius 0.2
move_face "MoveFace104"
sketch "Sketch75" plane through (17.9981, 0, 0) normal (-1, 0, 0) x axis (0, -1, 0)
  line L1 (-72.758, -24.2251) -> (-72.558, -24.22)
  line L2 (-72.558, 1) -> (-72.558, -24.22)
  line L3 (-70.058, 1) -> (-72.558, 1)
  line L4 (-70.058, 10) -> (-70.058, 1)
  line L5 (-144.3129, 10) -> (-70.058, 10)
  line L6 (-144.3129, -16.8091) -> (-144.3129, 10)
  line L7 (-125.7467, -4.8659) -> (-144.3129, -16.8091)
  line L8 (-72.758, 1) -> (-125.9366, 1)
  line L9 (-72.758, -24.2251) -> (-72.758, 1)
  line L10 (-72.758, 1) -> (-72.558, 1)
  arc A1 centre (-162.7924, -3.1291) radius 37.0864 clockwise from (-125.9366, 1) to (-125.7467, -4.8659)
  point P4 (-72.558, 1)
  point P13 (-72.558, 1)
  point P12 (-72.758, 1)
  point P14 (-72.758, 1)
  coincident P4 P13
  coincident P12 P14
extrude "Extrude72" cut sketch "Sketch75" profile of L3 L4 L5 L6 L7 A1 L8 L10 against normal blind 0.4
move_face "MoveFace105"
sketch "Sketch76" plane through (-17.9981, 0, 0) normal (1, 0, 0) x axis (0, 1, 0)
  line L1 (144.3129, -16.8091) -> (125.7467, -4.8659)
  line L2 (144.3129, 10) -> (144.3129, -16.8091)
  line L3 (70.058, 10) -> (144.3129, 10)
  line L4 (70.058, 1) -> (70.058, 10)
  line L5 (72.558, 1) -> (70.058, 1)
  line L6 (72.558, -24.2197) -> (72.558, 1)
  line L7 (72.558, -24.2197) -> (72.758, -24.2247)
  line L8 (72.758, 1) -> (72.758, -24.2247)
  line L9 (125.9366, 1) -> (72.758, 1)
  line L10 (72.758, 1) -> (72.558, 1)
  arc A1 centre (162.7924, -3.1291) radius 37.0864 clockwise from (125.7467, -4.8659) to (125.9366, 1)
  point P9 (72.558, 1)
  point P13 (72.558, 1)
  point P12 (72.758, 1)
  point P14 (72.758, 1)
  coincident P9 P13
  coincident P12 P14
extrude "Extrude73" cut sketch "Sketch76" profile of A1 L1 L2 L3 L4 L5 L9 L10 against normal blind 0.4
fillet "Fillet93" radius 2
move_face "MoveFace106"
sketch "Sketch77" plane through (0, 0, 10) normal (0, 0, 1) x axis (-1, 0, 0)
  line L1 (18.3981, -70.058) -> (8.4524, -70.058)
  line L2 (18.3981, -144.3129) -> (18.3981, -70.058)
  line L3 (19.9973, -144.3129) -> (18.3981, -144.3129)
  line L4 (19.9973, -21.0955) -> (19.9973, -144.3129)
  line L5 (17.9973, -19.0955) -> (19.9973, -21.0955)
  line L6 (8.4524, -19.0955) -> (17.9973, -19.0955)
  line L7 (8.4524, -70.058) -> (8.4524, -19.0955)
  line L8 (-18.3981, -70.058) -> (-18.3981, -144.3129)
  line L9 (-8.6845, -70.058) -> (-18.3981, -70.058)
  line L10 (-8.6845, -19.0955) -> (-8.6845, -70.058)
  line L11 (-17.9977, -19.0955) -> (-8.6845, -19.0955)
  line L12 (-19.9977, -21.0955) -> (-17.9977, -19.0955)
  line L13 (-19.9977, -144.3129) -> (-19.9977, -21.0955)
  line L14 (-18.3981, -144.3129) -> (-19.9977, -144.3129)
  line L15 (19.9973, -70.058) -> (18.3981, -70.058)
  line L16 (-19.9977, -70.058) -> (-18.3981, -70.058)
  line L17 (19.9973, -34.9535) -> (-19.9977, -34.9535)
  line L18 (19.9973, -54.3271) -> (-19.9977, -54.3271)
  point P3 (18.3981, -70.058)
  point P16 (18.3981, -70.058)
  point P17 (19.9973, -70.058)
  point P10 (-18.3981, -70.058)
  point P18 (-18.3981, -70.058)
  point P19 (-19.9977, -70.058)
  point P20 (-19.9977, -34.9535)
  point P21 (19.9973, -34.9535)
  point P22 (-19.9977, -54.3271)
  point P23 (19.9973, -54.3271)
  coincident P3 P16
  coincident L4 P17
  perpendicular L4 L15
  coincident P10 P18
  coincident L13 P19
  perpendicular L13 L16
  coincident L13 P20
  coincident L4 P21
  perpendicular L4 L17
  coincident L13 P22
  coincident L4 P23
  perpendicular L4 L18
extrude "Extrude74" new body sketch "Sketch77" profile of L1 L4 L5 L6 L7 L9 L10 L11 L12 L13 L15 L16 L17 L18 along normal blind 15
sketch "Sketch78" plane through (0, 0, 22) normal (0, 0, 1) x axis (-1, 0, 0)
  line L1 (6.9524, -152.6682) -> (-7.1845, -152.6682)
  line L2 (8.4524, -19.0955) -> (8.4524, -151.1682)
  line L3 (-8.6845, -19.0955) -> (8.4524, -19.0955)
  line L4 (-8.6845, -151.1682) -> (-8.6845, -19.0955)
  line L5 (10.7981, -70.258) -> (-10.7981, -70.258)
  arc A1 centre (-7.1845, -151.1682) radius 1.5 clockwise from (-7.1845, -152.6682) to (-8.6845, -151.1682)
  arc A2 centre (6.9524, -151.1682) radius 1.5 clockwise from (8.4524, -151.1682) to (6.9524, -152.6682)
extrude "Extrude75" new body sketch "Sketch78" profile of L2 L3 L4 L5 along normal blind 3
combine "Combine70"
combine "Combine71"
split "Split25" bodies "Barrel (1)"
split "Split26" bodies "Barrel (1) (1)"
mirror "Mirror23" mirrorStitchTolerance 0.1 bodies "Barrel (1) (1) (1)"
combine "Combine72" bodies "Barrel (1) (1)", "Barrel (1) (1) (1)"
combine "Combine73" bodies "Barrel (1)"
sketch "Sketch79" plane through (8.6845, 0, 0) normal (1, 0, 0) x axis (0, 1, 0)
  line L1 (153.85, 1) -> (19.0955, 1)
  line L2 (153.85, 4.75) -> (153.85, 1)
  line L3 (151.1689, 4.75) -> (153.85, 4.75)
  line L4 (151.1682, 4.75) -> (151.1689, 4.75)
  line L5 (151.1682, 8.5) -> (151.1682, 4.75)
  line L6 (85.6682, 8.5) -> (151.1682, 8.5)
  line L7 (151.1682, 14.5) -> (85.6682, 14.5)
  line L8 (151.1682, 22) -> (151.1682, 14.5)
  line L9 (70.258, 22) -> (151.1682, 22)
  line L10 (70.258, 25) -> (70.258, 22)
  line L11 (19.0955, 25) -> (70.258, 25)
  line L12 (19.0955, 1) -> (19.0955, 25)
  line L13 (85.6682, 10) -> (152.1682, 10)
  curve K1 (84.2267, 11.0852) -> (85.6682, 13.0239)
  line L14 (85.6682, 13.0239) -> (151.6603, 13.0239)
  curve K2 (151.6603, 13.0239) -> (152.6592, 14.003)
  line L15 (152.6682, 9.5) -> (152.6682, 4.75)
  curve K3 (152.6592, 14.003) -> (152.6682, 14.5233)
  line L16 (152.6682, 22) -> (152.6682, 14.5233)
  line L17 (152.6682, 9.5) -> (152.6592, 14.003)
  arc A1 centre (85.6682, 11.5) radius 3 clockwise from (85.6682, 8.5) to (85.6682, 14.5)
  arc A2 centre (85.6682, 11.5) radius 1.5 clockwise from (85.6682, 10) to (84.2267, 11.0852)
  arc A3 centre (152.1682, 9.5) radius 0.5 clockwise from (152.1682, 10) to (152.6682, 9.5)
  point P22 (152.6592, 14.003)
  point P28 (152.6592, 14.003)
  point P23 (152.6682, 9.5)
  point P29 (152.6682, 9.5)
  coincident P22 P28
  coincident P23 P29
delete_face "DeleteFace75"
move_face "MoveFace107"
move "Move59"
move_face "MoveFace108" TranslateX 0 TranslateY 0 TranslateZ 1
move_face "MoveFace109" TranslateX 0 TranslateY 0 TranslateZ 0.5
split "Split27" bodies "Barrel (1)", "Barrel (2)", "Barrel"
combine "Combine74" bodies "Barrel (2)"
delete_face "DeleteFace76"
delete_face "DeleteFace77"
delete_face "DeleteFace78"
remove_body "RemoveBody35"
remove_body "RemoveBody36"
fillet "Fillet94" radius 0.5
move_face "MoveFace110" RotateAngle -8
move_face "MoveFace111" TranslateX 0 TranslateY 2 TranslateZ 0
sketch "Sketch80" plane through (0, 155.85, 0) normal (0, 1, 0) x axis (-1, 0, 0)
  line L1 (-8.4524, 5.25) -> (8.4524, 5.25)
  line L2 (-8.4524, 1) -> (-8.4524, 5.25)
  line L3 (8.4524, 1) -> (-8.4524, 1)
  line L4 (8.4524, 5.25) -> (8.4524, 1)
  line L5 (-8.4524, 5.25) -> (-8.4524, 10)
  line L6 (8.4524, 5.25) -> (-8.4524, 5.25)
  line L7 (8.4524, 10) -> (8.4524, 5.25)
  line L8 (5.8059, 10) -> (8.4524, 10)
  line L9 (-8.4524, 10) -> (-5.806, 10)
  arc A1 centre (0, 13.7351) radius 6.9036 clockwise from (5.8059, 10) to (-5.806, 10)
extrude "Extrude76" new body sketch "Sketch80" along normal blind 2.1
move_face "MoveFace112" TranslateX -0.6 TranslateY 0 TranslateZ 0
move_face "MoveFace113" TranslateX 0.6 TranslateY 0 TranslateZ 0
move_face "MoveFace114" TranslateX 0 TranslateY 5.282 TranslateZ 0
